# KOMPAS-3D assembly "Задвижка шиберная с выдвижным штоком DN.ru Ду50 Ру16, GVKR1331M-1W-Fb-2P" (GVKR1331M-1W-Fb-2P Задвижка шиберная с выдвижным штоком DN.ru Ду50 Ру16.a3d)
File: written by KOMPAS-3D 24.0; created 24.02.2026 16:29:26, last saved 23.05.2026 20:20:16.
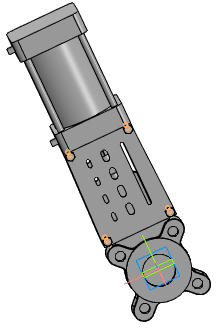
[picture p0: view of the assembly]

Document properties: Автор: R2D2; Полное имя файла: E:\Работа\Зайцев\GVKR1331M-1W-Fb-2P Задвижка шиберная с выдвижным штоком DN.ru Ду50-300 Ру16-10-6 с пневмоприводом\исходные материалы\DN50\GVKR1331M-1W-Fb-2P Задвижка шиберная с выдвижным штоком DN.ru Ду50 Ру16.a3d

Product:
- Component [detail]: Затвор дисковый DN.ru Ду Ру  | qty 1  | pos. 1  | Масса: 18.2; Раздел спецификации: Прочие изделия; Примечание: D050-23732; Автор: R2D2; source file: Задвижка шиберная РЕЗЬБОВОЙ DN.ru Ду Ру.m3d
- Component [detail]: Пневмоцилиндр  | qty 1  | pos. 2  | Масса: 15.361581; Автор: R2D2; source file: Пневмоцилиндр.m3d
- Component [standard]: Hexagon head screw ISO 4017 - М8 x 16  | qty 8  | Масса: 0.012085; Раздел спецификации: Стандартные изделия; Рассекать на разрезах: no
- Component [detail]: лист  | qty 2  | pos. 3  | Масса: 0.527465; Раздел спецификации: Прочие изделия; Примечание: D040-08800; Автор: R2D2; source file: лист.m3d
- Component [detail]: шибер  | qty 1  | pos. 4  | Масса: 0.384551; Раздел спецификации: Прочие изделия; Примечание: D040-08800; Автор: R2D2; source file: шибер.m3d
- Part/product: Задвижка шиберная с выдвижным штоком DN.ru Ду50 Ру16  | designation GVKR1331M-1W-Fb-2P
    Масса: 7
    Раздел спецификации: Прочие изделия
    Примечание: D040-08791

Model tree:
1. Контекстная связь:1  (with: Эскиз:1, Грань.Элемент выдавливания:15, Вершина.Элемент выдавливания:15, Ребро.Элемент выдавливания:15, Вершина.Элемент выдавливания:5, Ребро.Элемент выдавливания:5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)
2. Контекстная связь:2  (with: Эскиз:5, Ребро.Элемент выдавливания:15, Ребро.Элемент выдавливания:2, Ребро.Скругление:10, Ребро.Элемент выдавливания:1, Контекстная связь (шибер):2)
3. Контекстная связь:3  (with: Эскиз:4, Контекстная связь (Затвор дисковый DN.ru Ду Ру):3)
4. Контекстная связь:4  (with: Эскиз:5, Контекстная связь (Затвор дисковый DN.ru Ду Ру):4, Грань.Элемент выдавливания:8, Грань.Элемент выдавливания:3)  (labels: Грань.Элемент выдавливания:3.Экземпляр ( 2 ))
     Ориентация = 2; Ориентация = 2; Ориентация = 2; Ориентация = 2; Ориентация = 2

Expressions: D050-23732; D040-08800
Referenced files in E:\Работа\Зайцев\GVKR1331M-1W-Fb-2P Задвижка шиберная с выдвижным штоком DN.ru Ду50-300 Ру16-10-6 с пневмоприводом\исходные материалы\DN50\: Задвижка шиберная РЕЗЬБОВОЙ DN.ru Ду Ру.m3d, Пневмоцилиндр.m3d, лист.m3d, шибер.m3d
Referenced files in C:\Program Files\ASCON\KOMPAS-3D v24\Libs\PolynomLib\DATA\vault\Methods\Kompas\3D\: PLib_Bolt_1_ISO_1100.m3d
Referenced files in E:\Работа\Зайцев\GVKR1331E-1W-Fb-2P Задвижка шиберная DN.ru Ду50-300 Ру16-10-6\исходные материалы\DN50\111\: лист.m3d
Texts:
  WBV1631E-2W-Fb-R
  Затвор дисковый DN.ru Ду200 Ру16
  Hexagon head screw
  BOSimple***PART:17775d1c-e7de-f283-40f0-d40789f7f59e***SHORTLOC:A259_7B16EF33AB1642D2[13;1,25;16;8;-;Undefined]
  Программные изделия  и базы данных
  GVKR1331M-1W-Fb-2P
  Hexagon head screw ISO 4017 - М8 x 16 (1)
  hole1
  hole2
  Hexagon head screw ISO 4017 - М8 x 16 (2)
  Hexagon head screw ISO 4017 - М8 x 16 (3)
  Hexagon head screw ISO 4017 - М8 x 16 (4)
  лист (1)
  Hexagon head screw ISO 4017 - М8 x 16 (5)
  лист (2)
  Hexagon head screw ISO 4017 - М8 x 16 (6)
  Hexagon head screw ISO 4017 - М8 x 16 (7)
  Hexagon head screw ISO 4017 - М8 x 16 (8)
  Ось Y.Начало координат
  Плоскость ZY.Начало координат
  Плоскость ZX.Начало координат
  Плоскость XY.Начало координат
